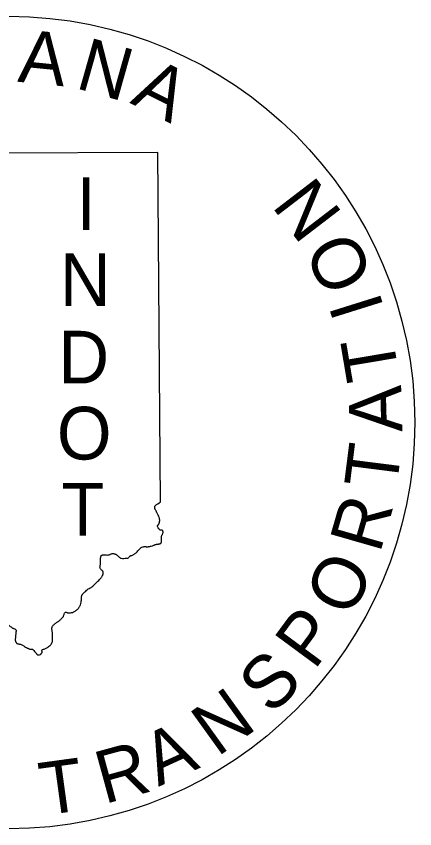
# Model space of a CAD drawing. Extents: x 0 to 3, y 0 to 2.
# Drawn here: x 1.5637 to 1.6274, y 1.5887 to 1.7186 of the extents above; entities that cross this region are included whole.
import ezdxf

# ---------------------------------------------------------------- set-up
doc = ezdxf.new("R2010")
doc.units = 0
doc.layers.add('Default', color=7, linetype='Continuous')
doc.layers.add('Sheet Border', color=7, linetype='Continuous')

msp = doc.modelspace()

# ---------------------------------------------------------------- linework, layer by layer
at = {"layer": 'Default'}
for p, q in [((1.58639, 1.6968), (1.55496, 1.6967)), ((1.58681, 1.64091), (1.58639, 1.6968))]:
    msp.add_line(p, q, dxfattribs=at)
for points in [[(1.58669, 1.63651), (1.58661, 1.63659), (1.58653, 1.63668), (1.58644, 1.63679), (1.58637, 1.63692), (1.58633, 1.6371), (1.58634, 1.6372), (1.58637, 1.63729), (1.5864, 1.63731), (1.58645, 1.63732), (1.58649, 1.63733), (1.58652, 1.63736), (1.58658, 1.63753), (1.58664, 1.63769), (1.58666, 1.63786), (1.58667, 1.63803), (1.58666, 1.63814), (1.58664, 1.63825), (1.58659, 1.63847), (1.58645, 1.63884), (1.58622, 1.63928), (1.58615, 1.63941), (1.58608, 1.63954), (1.586, 1.63967), (1.58593, 1.6398), (1.58588, 1.63996), (1.58587, 1.64004), (1.58587, 1.64012), (1.58588, 1.6402), (1.58591, 1.64028), (1.586, 1.64039), (1.58681, 1.64091)], [(1.58421, 1.63381), (1.5843, 1.63381), (1.58445, 1.63381), (1.5846, 1.6338), (1.58475, 1.6338), (1.58489, 1.63381), (1.5851, 1.63386), (1.5853, 1.63391), (1.58571, 1.63403), (1.5858, 1.63407), (1.58589, 1.63411), (1.58598, 1.63415), (1.58608, 1.63418), (1.5862, 1.63421), (1.58633, 1.63422), (1.58646, 1.63423), (1.58659, 1.63425), (1.58676, 1.6343), (1.58689, 1.6344), (1.58692, 1.63446), (1.58694, 1.63451), (1.58696, 1.63462), (1.58696, 1.63485), (1.58696, 1.63499), (1.58696, 1.63514), (1.58696, 1.63529), (1.58696, 1.63544), (1.587, 1.63557), (1.58706, 1.6357), (1.58714, 1.63583), (1.58718, 1.63596), (1.5872, 1.63618), (1.58717, 1.63629), (1.58711, 1.6364), (1.58703, 1.63645), (1.58693, 1.63645), (1.58683, 1.63644), (1.58674, 1.63647), (1.58669, 1.63651)], [(1.57976, 1.63253), (1.57997, 1.63235), (1.58006, 1.63227), (1.58016, 1.63218), (1.58025, 1.63211), (1.58034, 1.63204), (1.58053, 1.63196), (1.58135, 1.63196), (1.58149, 1.63196), (1.58166, 1.63202), (1.5818, 1.63216), (1.58193, 1.63231), (1.582, 1.63237), (1.58204, 1.63239), (1.58209, 1.63241), (1.58212, 1.63241), (1.58216, 1.6324), (1.5822, 1.6324), (1.58223, 1.63241), (1.58241, 1.6325), (1.58258, 1.6326), (1.58275, 1.63272), (1.5829, 1.63285), (1.58349, 1.63344), (1.58371, 1.63366), (1.58398, 1.63378), (1.58421, 1.63381)], [(1.57619, 1.62769), (1.57654, 1.62804), (1.57706, 1.62856), (1.5773, 1.62884), (1.5774, 1.62899), (1.5775, 1.62915), (1.57757, 1.62928), (1.57762, 1.62941), (1.57764, 1.62954), (1.57765, 1.62967), (1.57764, 1.62973), (1.57763, 1.62978), (1.57757, 1.62988), (1.57739, 1.63007), (1.57721, 1.63026), (1.57713, 1.63048), (1.57715, 1.63067), (1.57717, 1.63085), (1.5772, 1.63104), (1.57721, 1.63122), (1.57721, 1.63137), (1.57721, 1.63152), (1.57721, 1.63167), (1.57721, 1.63181), (1.57723, 1.63204), (1.57728, 1.63226), (1.57732, 1.63234), (1.57737, 1.63241), (1.5774, 1.63244), (1.57743, 1.63246), (1.5775, 1.63248), (1.57809, 1.63248), (1.57846, 1.63248), (1.57862, 1.63251), (1.57876, 1.63258), (1.57891, 1.63266), (1.57906, 1.6327), (1.57922, 1.63271), (1.57939, 1.63268), (1.57956, 1.63263), (1.57972, 1.63255), (1.57976, 1.63253)], [(1.57122, 1.62257), (1.57128, 1.62266), (1.57132, 1.62276), (1.57138, 1.62298), (1.57145, 1.62319), (1.57159, 1.62331), (1.57162, 1.62332), (1.57165, 1.62332), (1.57181, 1.6233), (1.57192, 1.62326), (1.57204, 1.62324), (1.5724, 1.62324), (1.57274, 1.62331), (1.57307, 1.62346), (1.57329, 1.62359), (1.57349, 1.62374), (1.57366, 1.62392), (1.57381, 1.62413), (1.57392, 1.62432), (1.574, 1.62452), (1.5741, 1.62494), (1.57418, 1.6256), (1.5742, 1.62583), (1.57425, 1.62605), (1.57429, 1.62613), (1.57434, 1.6262), (1.57445, 1.62633), (1.5747, 1.62657), (1.57499, 1.62686), (1.57526, 1.62706), (1.57555, 1.62722), (1.57584, 1.62739), (1.5761, 1.6276), (1.57619, 1.62769)], [(1.56916, 1.61804), (1.56921, 1.61809), (1.56937, 1.61828), (1.56943, 1.61837), (1.56948, 1.61846), (1.56952, 1.61865), (1.56952, 1.61895), (1.56952, 1.61998), (1.56951, 1.62019), (1.56948, 1.62039), (1.56945, 1.62059), (1.56945, 1.6208), (1.56947, 1.62089), (1.5695, 1.62099), (1.5696, 1.62116), (1.56974, 1.62132), (1.56989, 1.62146), (1.57007, 1.6216), (1.57026, 1.62173), (1.57045, 1.62185), (1.57063, 1.62198), (1.57079, 1.62212), (1.57094, 1.62227), (1.57122, 1.62257)], [(1.56217, 1.62137), (1.56217, 1.62143), (1.56221, 1.62146), (1.56223, 1.62147), (1.56225, 1.62147), (1.5623, 1.62145), (1.56242, 1.62137), (1.56247, 1.62132), (1.56253, 1.62127), (1.56265, 1.62117), (1.56291, 1.62098), (1.56317, 1.6208), (1.5633, 1.62073), (1.56345, 1.62068), (1.56358, 1.62061), (1.56368, 1.6205), (1.5637, 1.62047), (1.56371, 1.62045), (1.56372, 1.62039), (1.56372, 1.62028), (1.56368, 1.62006), (1.56367, 1.61987), (1.56365, 1.61969), (1.56363, 1.6195), (1.56361, 1.61932), (1.5636, 1.6191), (1.5636, 1.61887), (1.56369, 1.61854), (1.56376, 1.61843), (1.56379, 1.6184), (1.56382, 1.61837), (1.5639, 1.61833), (1.56405, 1.61828), (1.56415, 1.61827), (1.56424, 1.61825), (1.56434, 1.61824), (1.56442, 1.61821), (1.56463, 1.6181), (1.56483, 1.61799), (1.56503, 1.61788), (1.56504, 1.61787)], [(1.56504, 1.61787), (1.56524, 1.61777), (1.56553, 1.61761), (1.56568, 1.61754), (1.56583, 1.61747), (1.56595, 1.61744), (1.56609, 1.61744), (1.56622, 1.61744), (1.56635, 1.6174), (1.56641, 1.61735), (1.56647, 1.6173), (1.56658, 1.61719), (1.56679, 1.61695), (1.56686, 1.61686), (1.56694, 1.61677), (1.56701, 1.61667), (1.56708, 1.61658), (1.56719, 1.61652), (1.56733, 1.6165), (1.5676, 1.61658), (1.56765, 1.61662), (1.5677, 1.61666), (1.56778, 1.61675), (1.56784, 1.61685), (1.5679, 1.61695), (1.56789, 1.61703), (1.56785, 1.61711), (1.56781, 1.61718), (1.56782, 1.61725), (1.56787, 1.61729), (1.56791, 1.61732), (1.56801, 1.61737), (1.56822, 1.61745), (1.56844, 1.61752), (1.56864, 1.61762), (1.56883, 1.61776), (1.56902, 1.61792), (1.56916, 1.61804)]]:
    msp.add_spline(points, degree=3, dxfattribs=at)
at = {"layer": 'Sheet Border'}
msp.add_circle((1.5625, 1.65365), 0.06493, dxfattribs=at)

# ---------------------------------------------------------------- texts
for s, rotation, p in [('A', 354.2587, (1.56386, 1.70813)), ('N', 344.2016, (1.573, 1.70716)), ('A', 333.3036, (1.58178, 1.70476)), ('N', 127.4857, (1.61607, 1.68695)), ('O', 115.7415, (1.621, 1.67697)), ('I', 107.4105, (1.62256, 1.67192)), ('T', 99.5656, (1.62497, 1.66109)), ('A', 91.5933, (1.62545, 1.65219)), ('T', 82.7893, (1.62449, 1.6428)), ('R', 73.9631, (1.62184, 1.63258)), ('O', 63.5677, (1.61715, 1.62223)), ('P', 53.5776, (1.61138, 1.61393)), ('S', 45.007, (1.60452, 1.60671)), ('N', 35.7317, (1.59586, 1.6001)), ('A', 24.5837, (1.58647, 1.59541)), ('R', 15.2898, (1.57781, 1.59264)), ('T', 7.7944, (1.56807, 1.59084))]:
    msp.add_text(s, height=0.00842, rotation=rotation, dxfattribs=at).set_placement(p)
for s, p in [('I', (1.57336, 1.68443)), ('N', (1.57071, 1.67228)), ('D', (1.57047, 1.65989)), ('O', (1.57023, 1.64774)), ('T', (1.57096, 1.63559))]:
    msp.add_text(s, height=0.00842, dxfattribs=at).set_placement(p)

doc.saveas('drawing.dxf')
